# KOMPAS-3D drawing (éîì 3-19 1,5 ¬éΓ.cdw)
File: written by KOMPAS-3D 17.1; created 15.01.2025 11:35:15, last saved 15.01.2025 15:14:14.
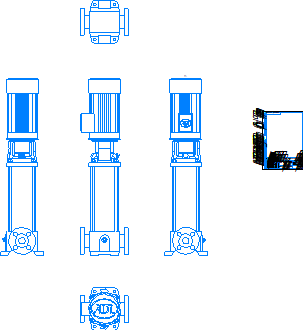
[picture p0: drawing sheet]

Sheet 1: A4, portrait

Title block, sheet 1: name: ВМН 3-19 1,5 кВт; designation: ВМН 3-19 1,5 кВт; material: Сталь 10  ГОСТ 1050-2013; mass: 68,16; sheets: 1; sheet format: A4; stored path: \\adlc.lan\data\АДЛ_ПКД\3D-модели\ADL production\Насосы ГРАНПАМП\Насосы ВМН\ВМН3\KOMPAS 3D\ВМН 3-19 1,5 кВт.cdw

Views: Проекционный вид 2, Проекционный вид 3, Проекционный вид 4, Проекционный вид 5
Referenced files in \\adlc.lan\data\АДЛ_ПКД\3D-модели\ADL production\Насосы ГРАНПАМП\Насосы ВМН\ВМН3\KOMPAS 3D\: ВМН 3-19 1,5 кВт.m3d
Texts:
  Andrey
  АДЛ
Dimensions and other numbers on the sheet: 1:1; 1; 68,16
